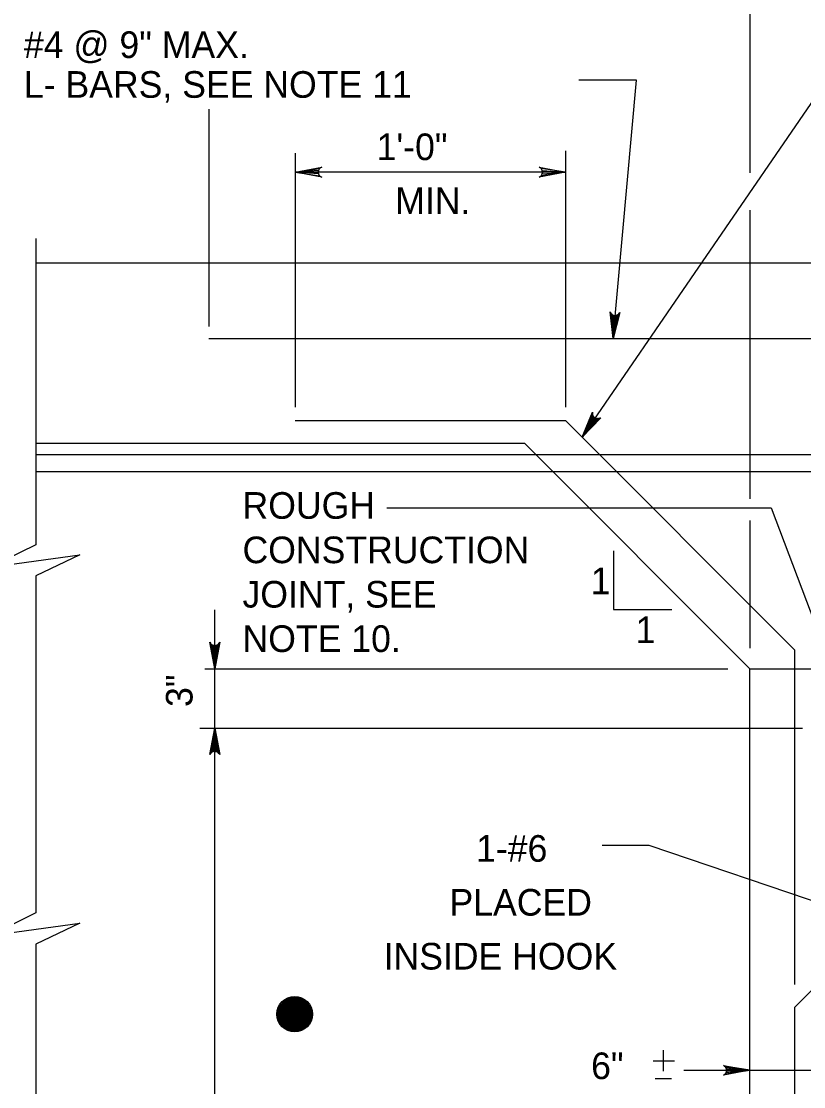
# Model space of a CAD drawing. Extents: x 640009 to 641706, y 298547 to 299735.
# Drawn here: x 640964.7 to 641052.8, y 299552.2 to 299672.2 of the extents above; entities that cross this region are included whole.
import ezdxf

# ---------------------------------------------------------------- set-up
doc = ezdxf.new("R2010")
doc.units = 0
doc.layers.add('1', color=7, linetype='Continuous')

msp = doc.modelspace()

# ---------------------------------------------------------------- linework, layer by layer
at = {"layer": '1'}
for p, q in [((641046.74, 299678.22), (641046.74, 299655.13)), ((641033.97, 299665.55), (641027.47, 299665.55)), ((641031.33, 299636.47), (641033.97, 299665.55)), ((641027.86, 299625.35), (641054.97, 299664.85)), ((640985.78, 299662.31), (640985.78, 299637.84)), ((640995.51, 299657.33), (640995.51, 299628.74)), ((641025.99, 299657.61), (641025.99, 299628.74)), ((641025.99, 299655.21), (640995.51, 299655.21)), ((641046.74, 299650.91), (641046.74, 299618.42)), ((640966.29, 299647.73), (640966.29, 299613.25)), ((640966.29, 299645), (641084.84, 299645)), ((640985.78, 299636.47), (641078.36, 299636.47)), ((640995.51, 299627.22), (641025.99, 299627.22)), ((641051.83, 299601.39), (641025.99, 299627.22)), ((640966.29, 299624.68), (641021.35, 299624.68)), ((641046.74, 299599.28), (641021.35, 299624.68)), ((640966.29, 299623.41), (641022.61, 299623.41)), ((641022.61, 299623.41), (641075.82, 299623.41)), ((640966.29, 299621.51), (641024.52, 299621.51)), ((641024.52, 299621.51), (641075.82, 299621.51)), ((641005.83, 299617.4), (641049.16, 299617.4)), ((641049.16, 299617.4), (641055.99, 299599.28)), ((641046.74, 299615.98), (641046.74, 299601.59)), ((641031.38, 299612.56), (641031.38, 299605.97)), ((640966.29, 299609.73), (640966.29, 299571.78)), ((640986.45, 299431.73), (640986.45, 299605.9)), ((641031.38, 299605.97), (641037.96, 299605.97)), ((641051.83, 299563.72), (641051.83, 299601.39)), ((640985.32, 299599.28), (641044.28, 299599.28)), ((641046.74, 299599.28), (641084.84, 299599.28)), ((641046.74, 299440.53), (641046.74, 299599.28)), ((640984.77, 299592.59), (641052.67, 299592.59)), ((641030.1, 299579.41), (641035.37, 299579.41)), ((641035.37, 299579.41), (641062.65, 299570.19)), ((640966.29, 299568.26), (640966.29, 299516.17)), ((641051.83, 299561.18), (641054.36, 299563.72)), ((641051.83, 299476.73), (641051.83, 299561.18)), ((641037, 299553.96), (641037, 299556.33)), ((641035.84, 299555.12), (641038.25, 299555.12)), ((641039.32, 299554.06), (641067.19, 299554.06)), ((641036.09, 299553.15), (641037.9, 299553.15))]:
    msp.add_line(p, q, dxfattribs=at)
for points in [[(640995.51, 299655.21), (640998.5, 299655.77), (640998.27, 299655.61), (640998.15, 299655.41), (640998.11, 299655.21), (640998.15, 299655.01), (640998.27, 299654.81), (640998.5, 299654.65), (640995.51, 299655.21), (640998.27, 299654.81), (640998.15, 299655.01), (640995.51, 299655.21), (640998.11, 299655.21), (640998.15, 299655.41), (640995.51, 299655.21), (640998.27, 299655.61)], [(641025.99, 299655.21), (641023.01, 299654.65), (641023.24, 299654.81), (641023.36, 299655.01), (641023.39, 299655.21), (641023.36, 299655.41), (641023.24, 299655.61), (641023.01, 299655.77), (641025.99, 299655.21), (641023.24, 299655.61), (641023.36, 299655.41), (641025.99, 299655.21), (641023.39, 299655.21), (641023.36, 299655.01), (641025.99, 299655.21), (641023.24, 299654.81)], [(641031.33, 299636.47), (641030.99, 299639.48), (641031.06, 299639.36), (641031.13, 299639.24), (641031.23, 299639.17), (641031.32, 299639.11), (641031.42, 299639.08), (641031.52, 299639.06), (641031.62, 299639.07), (641031.72, 299639.08), (641031.83, 299639.13), (641031.93, 299639.18), (641032.02, 299639.29), (641032.11, 299639.4), (641031.33, 299636.47), (641032.02, 299639.29), (641031.93, 299639.18), (641031.33, 299636.47), (641031.83, 299639.13), (641031.72, 299639.08), (641031.33, 299636.47), (641031.62, 299639.07), (641031.52, 299639.06), (641031.33, 299636.47), (641031.42, 299639.08), (641031.32, 299639.11), (641031.33, 299636.47), (641031.23, 299639.17), (641031.13, 299639.24), (641031.33, 299636.47), (641031.06, 299639.36)], [(641027.86, 299625.35), (641029.01, 299628.16), (641029.01, 299628.02), (641029.02, 299627.88), (641029.07, 299627.78), (641029.12, 299627.67), (641029.2, 299627.6), (641029.27, 299627.54), (641029.36, 299627.5), (641029.46, 299627.46), (641029.57, 299627.45), (641029.69, 299627.45), (641029.82, 299627.5), (641029.95, 299627.55), (641027.86, 299625.35), (641029.82, 299627.5), (641029.69, 299627.45), (641027.86, 299625.35), (641029.57, 299627.45), (641029.46, 299627.46), (641027.86, 299625.35), (641029.36, 299627.5), (641029.27, 299627.54), (641027.86, 299625.35), (641029.2, 299627.6), (641029.12, 299627.67), (641027.86, 299625.35), (641029.07, 299627.78), (641029.02, 299627.88), (641027.86, 299625.35), (641029.01, 299628.02)], [(640966.29, 299613.25), (640961.1, 299610.72), (640971.25, 299612.1), (640966.29, 299609.73)], [(640986.45, 299599.28), (640985.89, 299602.26), (640985.97, 299602.15), (640986.05, 299602.03), (640986.15, 299601.97), (640986.25, 299601.91), (640986.35, 299601.9), (640986.45, 299601.88), (640986.55, 299601.9), (640986.65, 299601.91), (640986.75, 299601.97), (640986.85, 299602.03), (640986.93, 299602.15), (640987.01, 299602.26), (640986.45, 299599.28), (640986.93, 299602.15), (640986.85, 299602.03), (640986.45, 299599.28), (640986.75, 299601.97), (640986.65, 299601.91), (640986.45, 299599.28), (640986.55, 299601.9), (640986.45, 299601.88), (640986.45, 299599.28), (640986.35, 299601.9), (640986.25, 299601.91), (640986.45, 299599.28), (640986.15, 299601.97), (640986.05, 299602.03), (640986.45, 299599.28), (640985.97, 299602.15)], [(640986.45, 299592.59), (640987.01, 299589.61), (640986.93, 299589.73), (640986.85, 299589.84), (640986.75, 299589.9), (640986.65, 299589.96), (640986.55, 299589.98), (640986.45, 299589.99), (640986.35, 299589.98), (640986.25, 299589.96), (640986.15, 299589.9), (640986.05, 299589.84), (640985.97, 299589.73), (640985.89, 299589.61), (640986.45, 299592.59), (640985.97, 299589.73), (640986.05, 299589.84), (640986.45, 299592.59), (640986.15, 299589.9), (640986.25, 299589.96), (640986.45, 299592.59), (640986.35, 299589.98), (640986.45, 299589.99), (640986.45, 299592.59), (640986.55, 299589.98), (640986.65, 299589.96), (640986.45, 299592.59), (640986.75, 299589.9), (640986.85, 299589.84), (640986.45, 299592.59), (640986.93, 299589.73)], [(640966.29, 299571.78), (640961.1, 299569.24), (640971.25, 299570.62), (640966.29, 299568.26)], [(640993.61, 299559.85), (640993.5, 299560.47), (640993.72, 299561.2), (640994.4, 299561.97), (640995.04, 299562.25), (640995.82, 299562.25), (640996.69, 299561.85), (640997.21, 299561.27), (640997.37, 299560.62), (640997.35, 299559.89), (640997.04, 299559.26), (640996.65, 299558.83), (640996.05, 299558.56), (640995.38, 299558.43), (640994.76, 299558.6), (640994.23, 299558.91), (640993.81, 299559.41), (640993.63, 299559.85), (640993.63, 299560.99), (640993.71, 299559.62), (640993.72, 299561.25), (640993.83, 299559.26), (640993.87, 299561.48), (640993.95, 299559.17), (640993.97, 299561.6), (640994.06, 299559.04), (640994.1, 299561.76), (640994.17, 299558.91), (640994.2, 299561.87), (640994.29, 299558.85), (640994.3, 299561.92), (640994.37, 299558.77), (640994.4, 299562.03), (640994.44, 299558.72), (640994.49, 299562.06), (640994.54, 299558.68), (640994.56, 299562.11), (640994.62, 299558.64), (640994.65, 299562.16), (640994.72, 299558.53), (640994.72, 299562.19), (640994.84, 299558.52), (640994.79, 299562.22), (640994.97, 299558.49), (640994.91, 299562.25), (640995.12, 299558.45), (640995.01, 299562.26), (640995.06, 299558.47), (640995.11, 299562.31), (640995.22, 299558.44), (640995.21, 299562.3), (640995.3, 299558.42), (640995.29, 299562.32), (640995.39, 299558.42), (640995.36, 299562.32), (640995.51, 299558.44), (640995.45, 299562.32), (640995.6, 299558.42), (640995.55, 299562.35), (640995.46, 299558.41), (640995.64, 299562.32), (640995.68, 299558.43), (640995.72, 299562.34), (640995.77, 299558.44), (640995.81, 299562.3), (640995.85, 299558.46), (640995.89, 299562.28), (640995.95, 299558.49), (640995.96, 299562.26), (640996.03, 299558.5), (640996.06, 299562.25), (640996.13, 299558.56), (640996.14, 299562.23), (640996.22, 299558.58), (640996.2, 299562.19), (640996.31, 299558.6), (640996.28, 299562.15), (640996.4, 299558.67), (640996.38, 299562.12), (640996.48, 299558.71), (640996.46, 299562.07), (640996.55, 299558.74), (640996.56, 299562.01), (640996.62, 299558.8), (640996.63, 299561.97), (640996.69, 299558.86), (640996.73, 299561.88), (640996.79, 299558.95), (640996.82, 299561.77), (640996.9, 299559.05), (640996.92, 299561.66), (640997.03, 299559.18), (640997, 299561.57), (640997.15, 299559.42), (640997.11, 299561.48), (640997.11, 299559.35), (640997.18, 299561.35), (640997.21, 299559.51), (640997.26, 299561.18), (640997.27, 299559.63), (640997.33, 299560.99)], [(640997.33, 299560.99), (640997.42, 299560.29), (640996.75, 299559.26), (640995.37, 299558.63), (640993.81, 299559.56), (640993.65, 299560.91), (640994.85, 299561.95), (640996.13, 299561.95), (640997.08, 299561.3), (640997.29, 299560.21), (640996.66, 299558.99), (640997.02, 299559.44), (640994.98, 299558.66), (640993.85, 299559.39), (640993.54, 299560.46), (640993.9, 299561.26), (640994.68, 299561.93), (640995.32, 299562.22), (640996.57, 299561.87)], [(641046.74, 299554.06), (641043.76, 299553.5), (641043.88, 299553.58), (641043.99, 299553.66), (641044.05, 299553.76), (641044.11, 299553.86), (641044.13, 299553.96), (641044.14, 299554.06), (641044.13, 299554.16), (641044.11, 299554.26), (641044.05, 299554.36), (641043.99, 299554.46), (641043.88, 299554.54), (641043.76, 299554.62), (641046.74, 299554.06), (641043.88, 299554.54), (641043.99, 299554.46), (641046.74, 299554.06), (641044.05, 299554.36), (641044.11, 299554.26), (641046.74, 299554.06), (641044.13, 299554.16), (641044.14, 299554.06), (641046.74, 299554.06), (641044.13, 299553.96), (641044.11, 299553.86), (641046.74, 299554.06), (641044.05, 299553.76), (641043.99, 299553.66), (641046.74, 299554.06), (641043.88, 299553.58)]]:
    msp.add_lwpolyline(points, dxfattribs=at)
msp.add_circle((640995.46, 299560.38), 2, dxfattribs=at)

# ---------------------------------------------------------------- texts
for s, p in [('#4 @ 9" MAX.', (640964.95, 299668.06)), ('L- BARS, SEE NOTE 11', (640964.95, 299663.58)), ('1\'-0"', (641004.69, 299656.56)), ('MIN.', (641006.79, 299650.48)), ('ROUGH', (640989.58, 299616.17)), ('CONSTRUCTION', (640989.58, 299611.17)), ('1', (641028.82, 299607.68)), ('JOINT, SEE', (640989.58, 299606.17)), ('1', (641033.88, 299602.17)), ('NOTE 10.', (640989.58, 299601.17)), ('1-#6', (641015.9, 299577.55)), ('PLACED', (641012.9, 299571.48)), ('INSIDE HOOK', (641005.48, 299565.41)), ('6"', (641028.86, 299553.07))]:
    msp.add_text(s, height=3, dxfattribs=at).set_placement(p)
msp.add_text('3"', height=3, rotation=90, dxfattribs=at).set_placement((640983.95, 299594.98))

doc.saveas('drawing.dxf')
